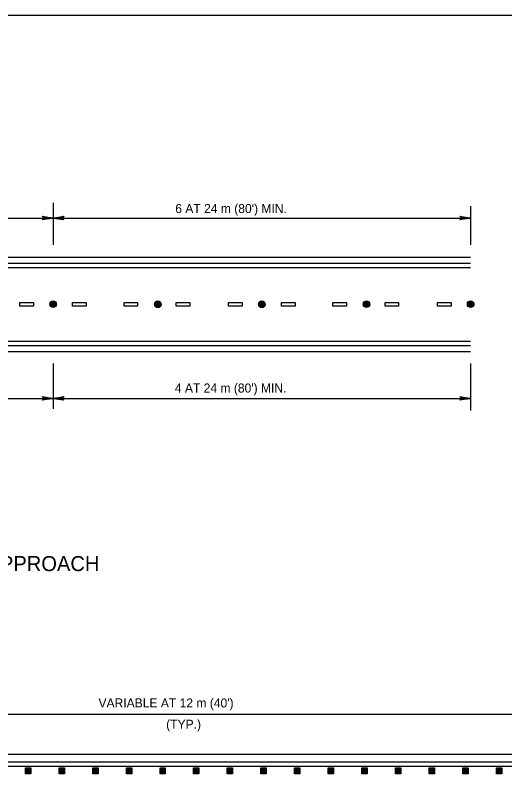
# Model space of a CAD drawing. Extents: x 639362 to 641108, y 298458 to 299646.
# Drawn here: x 639626 to 639788.7, y 298785.1 to 299037.2 of the extents above; entities that cross this region are included whole.
import ezdxf

# ---------------------------------------------------------------- set-up
doc = ezdxf.new("R2010")
doc.units = 0
for name, color, linetype in [('1', 7, 'Continuous'), ('2', 7, 'Continuous'), ('3', 7, 'Continuous')]:
    doc.layers.add(name, color=color, linetype=linetype)

# ---------------------------------------------------------------- blocks, each defined once
blk = doc.blocks.new('RARROW')
at = {"layer": '3'}
blk.add_lwpolyline([(-2.2695, 0.285), (-2.184875, 0.12075), (0, 0), (-2.2695, 0.285), (-2.38575, 0.384625), (0, 0), (-2.183125, -0.108), (-2.262875, -0.2705), (0, 0), (-2.38575, -0.379125), (-2.262875, -0.2705)], dxfattribs=at)

msp = doc.modelspace()

# ---------------------------------------------------------------- linework, layer by layer
at = {"layer": '1'}
msp.add_line((639403.27, 299037.19), (640189.27, 299037.19), dxfattribs=at)
at = {"layer": '2'}
for p, q in [((639638.59, 298974.82), (639638.59, 298960.81)), ((639777.38, 298973.77), (639777.38, 298960.81)), ((639466.77, 298969.77), (639638.59, 298969.77)), ((639638.59, 298969.77), (639777.38, 298969.77)), ((639465.63, 298956.81), (639777.38, 298956.81)), ((639465.63, 298954.81), (639777.38, 298954.81)), ((639465.63, 298953.31), (639777.38, 298953.31)), ((639465.63, 298928.88), (639777.38, 298928.88)), ((639465.63, 298927.38), (639777.38, 298927.38)), ((639465.63, 298925.38), (639777.38, 298925.38)), ((639638.59, 298921.38), (639638.59, 298906.38)), ((639777.38, 298921.38), (639777.38, 298905.84)), ((639466.77, 298909.84), (639638.59, 298909.84)), ((639638.59, 298909.84), (639777.38, 298909.84)), ((639585.52, 298804.88), (639797.99, 298804.88)), ((639431.25, 298791.58), (639952.64, 298791.58)), ((639431.25, 298789.08), (639952.64, 298789.08)), ((639431.25, 298787.58), (639952.64, 298787.58)), ((639629.37, 298787.09), (639631.15, 298787.09)), ((639629.37, 298785.05), (639629.37, 298787.09)), ((639629.55, 298786.92), (639630.97, 298786.92)), ((639629.55, 298785.23), (639629.55, 298786.92)), ((639629.73, 298786.74), (639630.79, 298786.74)), ((639629.73, 298785.41), (639629.73, 298786.74)), ((639629.9, 298785.59), (639629.9, 298786.56)), ((639629.9, 298786.56), (639630.61, 298786.56)), ((639630.08, 298786.39), (639630.44, 298786.39)), ((639630.08, 298785.76), (639630.08, 298786.39)), ((639630.44, 298785.76), (639630.08, 298785.76)), ((639630.26, 298786.21), (639630.26, 298785.94)), ((639630.44, 298786.39), (639630.44, 298785.76)), ((639630.61, 298786.56), (639630.61, 298785.59)), ((639630.79, 298786.74), (639630.79, 298785.41)), ((639630.97, 298786.92), (639630.97, 298785.23)), ((639631.15, 298787.09), (639631.15, 298785.05)), ((639640.55, 298787.09), (639642.33, 298787.09)), ((639640.55, 298785.05), (639640.55, 298787.09)), ((639640.73, 298786.92), (639642.15, 298786.92)), ((639640.73, 298785.23), (639640.73, 298786.92)), ((639640.91, 298786.74), (639641.97, 298786.74)), ((639640.91, 298785.41), (639640.91, 298786.74)), ((639641.09, 298785.59), (639641.09, 298786.56)), ((639641.09, 298786.56), (639641.8, 298786.56)), ((639641.26, 298786.39), (639641.62, 298786.39)), ((639641.26, 298785.76), (639641.26, 298786.39)), ((639641.62, 298785.76), (639641.26, 298785.76)), ((639641.44, 298786.21), (639641.44, 298785.94)), ((639641.62, 298786.39), (639641.62, 298785.76)), ((639641.8, 298786.56), (639641.8, 298785.59)), ((639641.97, 298786.74), (639641.97, 298785.41)), ((639642.15, 298786.92), (639642.15, 298785.23)), ((639642.33, 298787.09), (639642.33, 298785.05)), ((639651.74, 298787.09), (639653.51, 298787.09)), ((639651.74, 298785.05), (639651.74, 298787.09)), ((639651.92, 298786.92), (639653.33, 298786.92)), ((639651.92, 298785.23), (639651.92, 298786.92)), ((639652.09, 298786.74), (639653.16, 298786.74)), ((639652.09, 298785.41), (639652.09, 298786.74)), ((639652.27, 298785.59), (639652.27, 298786.56)), ((639652.27, 298786.56), (639652.98, 298786.56)), ((639652.45, 298786.39), (639652.8, 298786.39)), ((639652.45, 298785.76), (639652.45, 298786.39)), ((639652.8, 298785.76), (639652.45, 298785.76)), ((639652.62, 298786.21), (639652.62, 298785.94)), ((639652.8, 298786.39), (639652.8, 298785.76)), ((639652.98, 298786.56), (639652.98, 298785.59)), ((639653.16, 298786.74), (639653.16, 298785.41)), ((639653.33, 298786.92), (639653.33, 298785.23)), ((639653.51, 298787.09), (639653.51, 298785.05)), ((639662.92, 298787.09), (639664.7, 298787.09)), ((639662.92, 298785.05), (639662.92, 298787.09)), ((639663.1, 298786.92), (639664.52, 298786.92)), ((639663.1, 298785.23), (639663.1, 298786.92)), ((639663.28, 298786.74), (639664.34, 298786.74)), ((639663.28, 298785.41), (639663.28, 298786.74)), ((639663.45, 298785.59), (639663.45, 298786.56)), ((639663.45, 298786.56), (639664.16, 298786.56)), ((639663.63, 298786.39), (639663.99, 298786.39)), ((639663.63, 298785.76), (639663.63, 298786.39)), ((639663.99, 298785.76), (639663.63, 298785.76)), ((639663.81, 298786.21), (639663.81, 298785.94)), ((639663.99, 298786.39), (639663.99, 298785.76)), ((639664.16, 298786.56), (639664.16, 298785.59)), ((639664.34, 298786.74), (639664.34, 298785.41)), ((639664.52, 298786.92), (639664.52, 298785.23)), ((639664.7, 298787.09), (639664.7, 298785.05)), ((639674.11, 298787.09), (639675.88, 298787.09)), ((639674.11, 298785.05), (639674.11, 298787.09)), ((639674.28, 298786.92), (639675.7, 298786.92)), ((639674.28, 298785.23), (639674.28, 298786.92)), ((639674.46, 298786.74), (639675.53, 298786.74)), ((639674.46, 298785.41), (639674.46, 298786.74)), ((639674.64, 298785.59), (639674.64, 298786.56)), ((639674.64, 298786.56), (639675.35, 298786.56)), ((639674.82, 298786.39), (639675.17, 298786.39)), ((639674.82, 298785.76), (639674.82, 298786.39)), ((639675.17, 298785.76), (639674.82, 298785.76)), ((639674.99, 298786.21), (639674.99, 298785.94)), ((639675.17, 298786.39), (639675.17, 298785.76)), ((639675.35, 298786.56), (639675.35, 298785.59)), ((639675.53, 298786.74), (639675.53, 298785.41)), ((639675.7, 298786.92), (639675.7, 298785.23)), ((639675.88, 298787.09), (639675.88, 298785.05)), ((639685.29, 298787.09), (639687.06, 298787.09)), ((639685.29, 298785.05), (639685.29, 298787.09)), ((639685.47, 298786.92), (639686.89, 298786.92)), ((639685.47, 298785.23), (639685.47, 298786.92)), ((639685.64, 298786.74), (639686.71, 298786.74)), ((639685.64, 298785.41), (639685.64, 298786.74)), ((639685.82, 298785.59), (639685.82, 298786.56)), ((639685.82, 298786.56), (639686.53, 298786.56)), ((639686, 298786.39), (639686.35, 298786.39)), ((639686, 298785.76), (639686, 298786.39)), ((639686.35, 298785.76), (639686, 298785.76)), ((639686.17, 298786.21), (639686.17, 298785.94)), ((639686.35, 298786.39), (639686.35, 298785.76)), ((639686.53, 298786.56), (639686.53, 298785.59)), ((639686.71, 298786.74), (639686.71, 298785.41)), ((639686.89, 298786.92), (639686.89, 298785.23)), ((639687.06, 298787.09), (639687.06, 298785.05)), ((639696.47, 298787.09), (639698.25, 298787.09)), ((639696.47, 298785.05), (639696.47, 298787.09)), ((639696.65, 298786.92), (639698.07, 298786.92)), ((639696.65, 298785.23), (639696.65, 298786.92)), ((639696.83, 298786.74), (639697.89, 298786.74)), ((639696.83, 298785.41), (639696.83, 298786.74)), ((639697.01, 298785.59), (639697.01, 298786.56)), ((639697.01, 298786.56), (639697.71, 298786.56)), ((639697.18, 298786.39), (639697.54, 298786.39)), ((639697.18, 298785.76), (639697.18, 298786.39)), ((639697.54, 298785.76), (639697.18, 298785.76)), ((639697.36, 298786.21), (639697.36, 298785.94)), ((639697.54, 298786.39), (639697.54, 298785.76)), ((639697.71, 298786.56), (639697.71, 298785.59)), ((639697.89, 298786.74), (639697.89, 298785.41)), ((639698.07, 298786.92), (639698.07, 298785.23)), ((639698.25, 298787.09), (639698.25, 298785.05)), ((639707.66, 298787.09), (639709.43, 298787.09)), ((639707.66, 298785.05), (639707.66, 298787.09)), ((639707.83, 298786.92), (639709.25, 298786.92)), ((639707.83, 298785.23), (639707.83, 298786.92)), ((639708.01, 298786.74), (639709.08, 298786.74)), ((639708.01, 298785.41), (639708.01, 298786.74)), ((639708.19, 298785.59), (639708.19, 298786.56)), ((639708.19, 298786.56), (639708.9, 298786.56)), ((639708.37, 298786.39), (639708.72, 298786.39)), ((639708.37, 298785.76), (639708.37, 298786.39)), ((639708.72, 298785.76), (639708.37, 298785.76)), ((639708.54, 298786.21), (639708.54, 298785.94)), ((639708.72, 298786.39), (639708.72, 298785.76)), ((639708.9, 298786.56), (639708.9, 298785.59)), ((639709.08, 298786.74), (639709.08, 298785.41)), ((639709.25, 298786.92), (639709.25, 298785.23)), ((639709.43, 298787.09), (639709.43, 298785.05)), ((639718.84, 298787.09), (639720.62, 298787.09)), ((639718.84, 298785.05), (639718.84, 298787.09)), ((639719.02, 298786.92), (639720.44, 298786.92)), ((639719.02, 298785.23), (639719.02, 298786.92)), ((639719.2, 298786.74), (639720.26, 298786.74)), ((639719.2, 298785.41), (639719.2, 298786.74)), ((639719.37, 298785.59), (639719.37, 298786.56)), ((639719.37, 298786.56), (639720.08, 298786.56)), ((639719.55, 298786.39), (639719.91, 298786.39)), ((639719.55, 298785.76), (639719.55, 298786.39)), ((639719.91, 298785.76), (639719.55, 298785.76)), ((639719.73, 298786.21), (639719.73, 298785.94)), ((639719.91, 298786.39), (639719.91, 298785.76)), ((639720.08, 298786.56), (639720.08, 298785.59)), ((639720.26, 298786.74), (639720.26, 298785.41)), ((639720.44, 298786.92), (639720.44, 298785.23)), ((639720.62, 298787.09), (639720.62, 298785.05)), ((639730.02, 298787.09), (639731.8, 298787.09)), ((639730.02, 298785.05), (639730.02, 298787.09)), ((639730.2, 298786.92), (639731.62, 298786.92)), ((639730.2, 298785.23), (639730.2, 298786.92)), ((639730.38, 298786.74), (639731.44, 298786.74)), ((639730.38, 298785.41), (639730.38, 298786.74)), ((639730.56, 298785.59), (639730.56, 298786.56)), ((639730.56, 298786.56), (639731.27, 298786.56)), ((639730.73, 298786.39), (639731.09, 298786.39)), ((639730.73, 298785.76), (639730.73, 298786.39)), ((639731.09, 298785.76), (639730.73, 298785.76)), ((639730.91, 298786.21), (639730.91, 298785.94)), ((639731.09, 298786.39), (639731.09, 298785.76)), ((639731.27, 298786.56), (639731.27, 298785.59)), ((639731.44, 298786.74), (639731.44, 298785.41)), ((639731.62, 298786.92), (639731.62, 298785.23)), ((639731.8, 298787.09), (639731.8, 298785.05)), ((639741.21, 298787.09), (639742.98, 298787.09)), ((639741.21, 298785.05), (639741.21, 298787.09)), ((639741.39, 298786.92), (639742.8, 298786.92)), ((639741.39, 298785.23), (639741.39, 298786.92)), ((639741.56, 298786.74), (639742.63, 298786.74)), ((639741.56, 298785.41), (639741.56, 298786.74)), ((639741.74, 298785.59), (639741.74, 298786.56)), ((639741.74, 298786.56), (639742.45, 298786.56)), ((639741.92, 298786.39), (639742.27, 298786.39)), ((639741.92, 298785.76), (639741.92, 298786.39)), ((639742.27, 298785.76), (639741.92, 298785.76)), ((639742.09, 298786.21), (639742.09, 298785.94)), ((639742.27, 298786.39), (639742.27, 298785.76)), ((639742.45, 298786.56), (639742.45, 298785.59)), ((639742.63, 298786.74), (639742.63, 298785.41)), ((639742.8, 298786.92), (639742.8, 298785.23)), ((639742.98, 298787.09), (639742.98, 298785.05)), ((639752.39, 298787.09), (639754.17, 298787.09)), ((639752.39, 298785.05), (639752.39, 298787.09)), ((639752.57, 298786.92), (639753.99, 298786.92)), ((639752.57, 298785.23), (639752.57, 298786.92)), ((639752.75, 298786.74), (639753.81, 298786.74)), ((639752.75, 298785.41), (639752.75, 298786.74)), ((639752.92, 298785.59), (639752.92, 298786.56)), ((639752.92, 298786.56), (639753.63, 298786.56)), ((639753.1, 298786.39), (639753.46, 298786.39)), ((639753.1, 298785.76), (639753.1, 298786.39)), ((639753.46, 298785.76), (639753.1, 298785.76)), ((639753.28, 298786.21), (639753.28, 298785.94)), ((639753.46, 298786.39), (639753.46, 298785.76)), ((639753.63, 298786.56), (639753.63, 298785.59)), ((639753.81, 298786.74), (639753.81, 298785.41)), ((639753.99, 298786.92), (639753.99, 298785.23)), ((639754.17, 298787.09), (639754.17, 298785.05)), ((639763.58, 298787.09), (639765.35, 298787.09)), ((639763.58, 298785.05), (639763.58, 298787.09)), ((639763.75, 298786.92), (639765.17, 298786.92)), ((639763.75, 298785.23), (639763.75, 298786.92)), ((639763.93, 298786.74), (639765, 298786.74)), ((639763.93, 298785.41), (639763.93, 298786.74)), ((639764.11, 298785.59), (639764.11, 298786.56)), ((639764.11, 298786.56), (639764.82, 298786.56)), ((639764.29, 298786.39), (639764.64, 298786.39)), ((639764.29, 298785.76), (639764.29, 298786.39)), ((639764.64, 298785.76), (639764.29, 298785.76)), ((639764.46, 298786.21), (639764.46, 298785.94)), ((639764.64, 298786.39), (639764.64, 298785.76)), ((639764.82, 298786.56), (639764.82, 298785.59)), ((639765, 298786.74), (639765, 298785.41)), ((639765.17, 298786.92), (639765.17, 298785.23)), ((639765.35, 298787.09), (639765.35, 298785.05)), ((639774.76, 298787.09), (639776.53, 298787.09)), ((639774.76, 298785.05), (639774.76, 298787.09)), ((639774.94, 298786.92), (639776.36, 298786.92)), ((639774.94, 298785.23), (639774.94, 298786.92)), ((639775.11, 298786.74), (639776.18, 298786.74)), ((639775.11, 298785.41), (639775.11, 298786.74)), ((639775.29, 298785.59), (639775.29, 298786.56)), ((639775.29, 298786.56), (639776, 298786.56)), ((639775.47, 298786.39), (639775.82, 298786.39)), ((639775.47, 298785.76), (639775.47, 298786.39)), ((639775.82, 298785.76), (639775.47, 298785.76)), ((639775.64, 298786.21), (639775.64, 298785.94)), ((639775.82, 298786.39), (639775.82, 298785.76)), ((639776, 298786.56), (639776, 298785.59)), ((639776.18, 298786.74), (639776.18, 298785.41)), ((639776.36, 298786.92), (639776.36, 298785.23)), ((639776.53, 298787.09), (639776.53, 298785.05)), ((639785.94, 298787.09), (639787.72, 298787.09)), ((639785.94, 298785.05), (639785.94, 298787.09)), ((639786.12, 298786.92), (639787.54, 298786.92)), ((639786.12, 298785.23), (639786.12, 298786.92)), ((639786.3, 298786.74), (639787.36, 298786.74)), ((639786.3, 298785.41), (639786.3, 298786.74)), ((639786.48, 298785.59), (639786.48, 298786.56)), ((639786.48, 298786.56), (639787.18, 298786.56)), ((639786.65, 298786.39), (639787.01, 298786.39)), ((639786.65, 298785.76), (639786.65, 298786.39)), ((639787.01, 298785.76), (639786.65, 298785.76)), ((639786.83, 298786.21), (639786.83, 298785.94)), ((639787.01, 298786.39), (639787.01, 298785.76)), ((639787.18, 298786.56), (639787.18, 298785.59)), ((639787.36, 298786.74), (639787.36, 298785.41)), ((639787.54, 298786.92), (639787.54, 298785.23)), ((639787.72, 298787.09), (639787.72, 298785.05)), ((639631.15, 298785.05), (639629.37, 298785.05)), ((639630.97, 298785.23), (639629.55, 298785.23)), ((639630.79, 298785.41), (639629.73, 298785.41)), ((639630.61, 298785.59), (639629.9, 298785.59)), ((639642.33, 298785.05), (639640.55, 298785.05)), ((639642.15, 298785.23), (639640.73, 298785.23)), ((639641.97, 298785.41), (639640.91, 298785.41)), ((639641.8, 298785.59), (639641.09, 298785.59)), ((639653.51, 298785.05), (639651.74, 298785.05)), ((639653.33, 298785.23), (639651.92, 298785.23)), ((639653.16, 298785.41), (639652.09, 298785.41)), ((639652.98, 298785.59), (639652.27, 298785.59)), ((639664.7, 298785.05), (639662.92, 298785.05)), ((639664.52, 298785.23), (639663.1, 298785.23)), ((639664.34, 298785.41), (639663.28, 298785.41)), ((639664.16, 298785.59), (639663.45, 298785.59)), ((639675.88, 298785.05), (639674.11, 298785.05)), ((639675.7, 298785.23), (639674.28, 298785.23)), ((639675.53, 298785.41), (639674.46, 298785.41)), ((639675.35, 298785.59), (639674.64, 298785.59)), ((639687.06, 298785.05), (639685.29, 298785.05)), ((639686.89, 298785.23), (639685.47, 298785.23)), ((639686.71, 298785.41), (639685.64, 298785.41)), ((639686.53, 298785.59), (639685.82, 298785.59)), ((639698.25, 298785.05), (639696.47, 298785.05)), ((639698.07, 298785.23), (639696.65, 298785.23)), ((639697.89, 298785.41), (639696.83, 298785.41)), ((639697.71, 298785.59), (639697.01, 298785.59)), ((639709.43, 298785.05), (639707.66, 298785.05)), ((639709.25, 298785.23), (639707.83, 298785.23)), ((639709.08, 298785.41), (639708.01, 298785.41)), ((639708.9, 298785.59), (639708.19, 298785.59)), ((639720.62, 298785.05), (639718.84, 298785.05)), ((639720.44, 298785.23), (639719.02, 298785.23)), ((639720.26, 298785.41), (639719.2, 298785.41)), ((639720.08, 298785.59), (639719.37, 298785.59)), ((639731.8, 298785.05), (639730.02, 298785.05)), ((639731.62, 298785.23), (639730.2, 298785.23)), ((639731.44, 298785.41), (639730.38, 298785.41)), ((639731.27, 298785.59), (639730.56, 298785.59)), ((639742.98, 298785.05), (639741.21, 298785.05)), ((639742.8, 298785.23), (639741.39, 298785.23)), ((639742.63, 298785.41), (639741.56, 298785.41)), ((639742.45, 298785.59), (639741.74, 298785.59)), ((639754.17, 298785.05), (639752.39, 298785.05)), ((639753.99, 298785.23), (639752.57, 298785.23)), ((639753.81, 298785.41), (639752.75, 298785.41)), ((639753.63, 298785.59), (639752.92, 298785.59)), ((639765.35, 298785.05), (639763.58, 298785.05)), ((639765.17, 298785.23), (639763.75, 298785.23)), ((639765, 298785.41), (639763.93, 298785.41)), ((639764.82, 298785.59), (639764.11, 298785.59)), ((639776.53, 298785.05), (639774.76, 298785.05)), ((639776.36, 298785.23), (639774.94, 298785.23)), ((639776.18, 298785.41), (639775.11, 298785.41)), ((639776, 298785.59), (639775.29, 298785.59)), ((639787.72, 298785.05), (639785.94, 298785.05)), ((639787.54, 298785.23), (639786.12, 298785.23)), ((639787.36, 298785.41), (639786.3, 298785.41)), ((639787.18, 298785.59), (639786.48, 298785.59))]:
    msp.add_line(p, q, dxfattribs=at)
for points in [[(639627.51, 298941.72), (639632.03, 298941.72), (639632.03, 298940.52), (639627.51, 298940.52)], [(639645.01, 298941.72), (639649.53, 298941.72), (639649.53, 298940.52), (639645.01, 298940.52)], [(639662.14, 298941.72), (639666.66, 298941.72), (639666.66, 298940.52), (639662.14, 298940.52)], [(639679.51, 298941.72), (639684.03, 298941.72), (639684.03, 298940.52), (639679.51, 298940.52)], [(639696.92, 298941.72), (639701.44, 298941.72), (639701.44, 298940.52), (639696.92, 298940.52)], [(639714.5, 298941.72), (639719.02, 298941.72), (639719.02, 298940.52), (639714.5, 298940.52)], [(639731.55, 298941.72), (639736.08, 298941.72), (639736.08, 298940.52), (639731.55, 298940.52)], [(639748.93, 298941.72), (639753.45, 298941.72), (639753.45, 298940.52), (639748.93, 298940.52)], [(639766.4, 298941.72), (639770.92, 298941.72), (639770.92, 298940.52), (639766.4, 298940.52)]]:
    msp.add_lwpolyline(points, close=True, dxfattribs=at)
for centre, radius in [((639638.6, 298941.11), 1.1), ((639638.6, 298941.11), 1.02), ((639673.37, 298941.1), 1.1), ((639673.37, 298941.1), 1.02), ((639707.94, 298941.1), 1.1), ((639707.94, 298941.1), 1.02), ((639742.79, 298941.12), 1.1), ((639742.79, 298941.12), 1.02), ((639777.38, 298941.12), 1.1), ((639777.38, 298941.12), 1.02), ((639638.6, 298941.11), 0.946), ((639638.6, 298941.11), 0.868), ((639638.6, 298941.11), 0.789), ((639638.6, 298941.11), 0.711), ((639638.6, 298941.11), 0.633), ((639638.6, 298941.11), 0.554), ((639638.6, 298941.11), 0.476), ((639638.6, 298941.11), 0.398), ((639638.6, 298941.11), 0.32), ((639638.6, 298941.11), 0.241), ((639638.6, 298941.11), 0.163), ((639638.6, 298941.11), 0.0846), ((639673.37, 298941.1), 0.946), ((639673.37, 298941.1), 0.868), ((639673.37, 298941.1), 0.789), ((639673.37, 298941.1), 0.711), ((639673.37, 298941.1), 0.633), ((639673.37, 298941.1), 0.554), ((639673.37, 298941.1), 0.476), ((639673.37, 298941.1), 0.398), ((639673.37, 298941.1), 0.32), ((639673.37, 298941.1), 0.241), ((639673.37, 298941.1), 0.163), ((639673.37, 298941.1), 0.0846), ((639707.94, 298941.1), 0.946), ((639707.94, 298941.1), 0.868), ((639707.94, 298941.1), 0.789), ((639707.94, 298941.1), 0.711), ((639707.94, 298941.1), 0.633), ((639707.94, 298941.1), 0.554), ((639707.94, 298941.1), 0.476), ((639707.94, 298941.1), 0.398), ((639707.94, 298941.1), 0.32), ((639707.94, 298941.1), 0.241), ((639707.94, 298941.1), 0.163), ((639707.94, 298941.1), 0.0846), ((639742.79, 298941.12), 0.946), ((639742.79, 298941.12), 0.868), ((639742.79, 298941.12), 0.789), ((639742.79, 298941.12), 0.711), ((639742.79, 298941.12), 0.633), ((639742.79, 298941.12), 0.554), ((639742.79, 298941.12), 0.476), ((639742.79, 298941.12), 0.398), ((639742.79, 298941.12), 0.32), ((639742.79, 298941.12), 0.241), ((639742.79, 298941.12), 0.163), ((639742.79, 298941.12), 0.0846), ((639777.38, 298941.12), 0.946), ((639777.38, 298941.12), 0.868), ((639777.38, 298941.12), 0.789), ((639777.38, 298941.12), 0.711), ((639777.38, 298941.12), 0.633), ((639777.38, 298941.12), 0.554), ((639777.38, 298941.12), 0.476), ((639777.38, 298941.12), 0.398), ((639777.38, 298941.12), 0.32), ((639777.38, 298941.12), 0.241), ((639777.38, 298941.12), 0.163), ((639777.38, 298941.12), 0.0846)]:
    msp.add_circle(centre, radius, dxfattribs=at)

# ---------------------------------------------------------------- block references
at = {"layer": '2', "xscale": 1.5089217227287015, "yscale": 1.5711553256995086}
for p in [(639638.59, 298969.77), (639777.38, 298969.77), (639638.59, 298909.84), (639777.38, 298909.84)]:
    msp.add_blockref('RARROW', p, dxfattribs=at)
at = {"layer": '2', "xscale": 1.5089217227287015, "yscale": 1.5711553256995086, "rotation": 180}
for p in [(639638.59, 298969.77), (639638.59, 298909.84)]:
    msp.add_blockref('RARROW', p, dxfattribs=at)

# ---------------------------------------------------------------- texts
at = {"layer": '2'}
for s, height, p in [("6 AT 24 m (80') MIN.", 3, (639679.18, 298971.43)), ("4 AT 24 m (80') MIN.", 3, (639679.04, 298911.78)), ('INTERSECTION APPROACH', 5, (639564.81, 298852.43)), ("VARIABLE AT 12 m (40')", 3, (639653.65, 298807.11)), ('(TYP.)', 3, (639676.16, 298800.03))]:
    msp.add_text(s, height=height, dxfattribs=at).set_placement(p)

doc.saveas('drawing.dxf')
